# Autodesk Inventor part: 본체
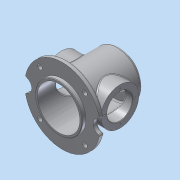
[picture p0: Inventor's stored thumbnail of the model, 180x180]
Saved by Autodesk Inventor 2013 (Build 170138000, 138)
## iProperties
Created: 2018-04
Part Number: 본체
Material: 알루미늄 6061
Document SubType Name: Modeling
Designer: dgall
Density: 2.71 g/cm^3
Mass: 1151.24 g
Surface Area: 1200.37 cm^2
Volume: 424.812 cm^3
Author: dgall
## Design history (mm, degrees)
node "작업 평면1"
sketch "스케치2"
  geometry: L1 (40, 0)-(40, 124) reference; C1 r 50 at (0, 62); 2 further points
  constraints: 1 centre point, 1 horizontal alignment, 1 midpoint, 1 vertical alignment
  dimensions: "d4" = 100 diameter of C1
extrude "돌출2" join sketch "스케치2" distance "d5" = 128; taper "d6" = 0 deg
fillet "모깎기1" dims "d7" = 5
sketch "스케치3"
  geometry: C1 r 45 at (0, 0) reference; C2 r 40 at (0, 0); 1 further point
  constraints: 1 centre point, 1 coincident
  dimensions: "d10" = 80 diameter of C2
extrude "돌출3" join sketch "스케치3" distance "d11" = 5; taper "d12" = 0 deg
node "작업 평면2"
sketch "스케치4"
  geometry: L1 (55, 22)-(55, 102) reference; L2 (-78, 112)-(-78, 12) reference; C1 r 40 at (-10, 62); 2 further points
  constraints: 1 centre point, 1 horizontal alignment, 1 midpoint
  dimensions: "d14" = 80 diameter of C1; "d15" = 68 distance from line of L2 C1.centre
extrude "돌출4" join sketch "스케치4" distance "d16" = 124; taper "d17" = 0 deg
sketch "스케치5"
  geometry: C1 r 45 at (0, 0) reference; C2 r 50 at (0, 0) reference; C3 r 45 at (0, 0); 1 further point
  constraints: 1 centre point, 1 coincident
  dimensions: "d18" = 90 diameter of C3
extrude "돌출5" cut sketch "스케치5" distance "d20" = 120; taper "d21" = 0 deg
sketch "스케치6"
  geometry: C1 r 40 at (0, 0) reference; C2 r 27 at (0, 0); 1 further point
  constraints: 1 centre point, 1 coincident
  dimensions: "d22" = 54 diameter of C2
extrude "돌출6" cut sketch "스케치6" stored distance "d23" = 110; taper "d24" = 0 deg
node "작업 평면3"
sketch "스케치7"
  geometry: C1 r 50 at (0, 0) reference; C2 r 80 at (0, 0); 1 further point
  constraints: 2 coincident, 1 centre point
  dimensions: "d27" = 160 diameter of C2
extrude "돌출7" join sketch "스케치7" distance "d28" = 10; taper "d29" = 0 deg
sketch "스케치8" dims "d30" = 135
  geometry: L1 (-47.73, 47.73)-(0, 0); L2 (0, 0)-(0, 80); 3 further points
  constraints: 4 end point, 2 coincident, 1 vertical, 1 vertical alignment, 4 other
  dimensions: "d32" = 45 deg angle of L2 L1
hole "구멍1" sketch "스케치8" at (-47.73, 47.73) diameter "d34" = 10; stored, may be unused: countersink angle "d38" = 90 deg, drill point angle "d40" = 118 deg; dims "d35" = 6, "d36" = 4, "d37" = 2, "d39" = 8
node "작업 평면4"
node "작업 평면5"
sketch "스케치10"
  geometry: C1 r 50 at (0, 0) reference; C2 r 15 at (-80, 0); C3 r 15 at (80, 0); A1 r 80 centre (0, 0) between (-80, 0) and (80, 0) reference; A2 r 80 centre (0, 0) between (-80, 0) and (80, 0) reference; 1 further point
  constraints: 4 point on circle, 2 centre point, 2 horizontal alignment
  dimensions: "d42" = 30 diameter of C2; "d43" = 30 diameter of C3
extrude "돌출8" cut sketch "스케치10" stored distance "d44" = 10; taper "d45" = 0 deg
fillet "모깎기3" dims "d46" = 3
sketch "스케치12"
  geometry: C1 r 40 at (0, 0) reference; C2 r 27 at (0, 0); 1 further point
  constraints: 1 centre point, 1 coincident
  dimensions: "d47" = 54 diameter of C2
chamfer "모따기1" distance "d62" = 1; stored, may be unused: second distance "d63" = 2, angle "d64" = 45 deg
sketch "스케치15"
  geometry: C1 r 40 at (0, 0) reference; 5 further points
  constraints: 1 vertical alignment, 5 other
  dimensions: "d65" = 32.5 distance of C1.centre point (0, 32.5); "d68" = 360 deg dimension on C1.centre point (0, 32.5) (derived)
hole "구멍3" sketch "스케치15" at (0, 32.5), (-32.5, 0), (0, -32.5), (32.5, 0) diameter "d70" = 3.242; stored, may be unused: countersink angle "d74" = 90 deg, drill point angle "d76" = 118 deg; dims "d71" = 8, "d72" = 4, "d73" = 2, "d75" = 10
sketch "스케치16"
  geometry: C1 r 40 at (0, 0) reference; 5 further points
  constraints: 1 vertical alignment, 5 other
  dimensions: "d77" = 32.5 distance of C1.centre point (0, 32.5); "d80" = 360 deg dimension on C1.centre point (0, 32.5) (derived)
hole "구멍4" sketch "스케치16" at (0, 32.5), (-32.5, 0), (0, -32.5), (32.5, 0) diameter "d82" = 3.242; stored, may be unused: countersink angle "d86" = 90 deg, drill point angle "d88" = 118 deg; dims "d83" = 8, "d84" = 4, "d85" = 2, "d87" = 10
fillet "모깎기4" dims "d89" = 3
fillet "모깎기5" dims "d90" = 3
chamfer "모따기2" distance "d91" = 1; stored, may be unused: second distance "d92" = 2, angle "d93" = 45 deg
fillet "모깎기6" dims "d94" = 3
extrude "돌출10" cut sketch "스케치12" stored distance "d95" = 10; taper "d96" = 0 deg
chamfer "모따기3" distance "d97" = 1; stored, may be unused: second distance "d98" = 2, angle "d99" = 45 deg
fillet "모깎기7" dims "d100" = 3
node "작업 평면6"
sketch "스케치19"
  geometry: L1 (-77.955, -70)-(77.955, -70) reference; 2 further points
  constraints: 1 coincident, 1 other
  dimensions: "d102" = 70 distance from line of L1 point (0, 0)
feature "엠보싱1" sketch "스케치19" dims "d4" = 100, "d16" = 124, "d103" = 0.5, "d104" = 0
sketch "스케치20"
  geometry: C1 r 40 at (0, 0) reference; 5 further points
  constraints: 1 vertical alignment, 5 other
  dimensions: "d105" = 32.5 distance of C1.centre point (0, 32.5); "d108" = 360 deg dimension on C1.centre point (0, 32.5) (derived)
hole "구멍5" sketch "스케치20" at (0, 32.5), (-32.5, 0), (0, -32.5), (32.5, 0) diameter "d110" = 3.242; stored, may be unused: countersink angle "d114" = 82 deg, drill point angle "d116" = 118 deg; dims "d111" = 8, "d112" = 3.023, "d113" = 2, "d115" = 10
node "솔리드1"
mirror "대칭1"
mirror "대칭2"
other parameters: "d13" = 62, "d25" = -8, "d41" = 62, "d101" = -24.75
